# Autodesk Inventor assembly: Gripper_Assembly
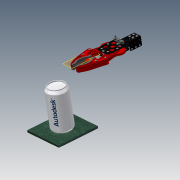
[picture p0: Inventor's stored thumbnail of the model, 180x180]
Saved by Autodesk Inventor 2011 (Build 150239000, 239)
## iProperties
Created: 2007-10
Part Number: Gripper_Assembly
Document SubType Name: Assembly
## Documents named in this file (10)
- C:\Data Folder\VEX 2011\Inventor Datasets\Unit 12\Gripper_Assembly.iam
- C:\Data Folder\VEX 2011\Inventor Datasets\Unit 12\Components\Vexplorer-Claw-Pin.iam
- C:\Data Folder\VEX 2011\Inventor Datasets\Unit 12\Components\Vexplorer-CLAW-FINGER-ASSY.iam
- C:\Data Folder\VEX 2011\Inventor Datasets\Unit 12\Components\VEX-12-TOOTH-GEAR.ipt
- C:\Data Folder\VEX 2011\Inventor Datasets\Unit 12\Components\Vexplorer-CLAW-GEAR-LINKAGE.ipt
- C:\Data Folder\VEX 2011\Inventor Datasets\Unit 12\Components\Vexplorer-CLAW-LINKAGE.ipt
- C:\Data Folder\VEX 2011\Inventor Datasets\Unit 12\Components\SHAFT-2000.ipt
- C:\Data Folder\VEX 2011\Inventor Datasets\Unit 12\Gripper_Assembly_SubAssembly.iam
- C:\Data Folder\VEX 2011\Inventor Datasets\Unit 12\Components\Base_01.ipt
- C:\Data Folder\VEX 2011\Inventor Datasets\Unit 12\Components\Can.ipt
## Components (15 placed, 9 different names)
1. Vexplorer-CLAW-FINGER-ASSY [sub-assembly] — Mate:56, Mate:57, Mate:58, Mate:63, Mate:64, Mate:65, Mate:66
2. VEX-12-TOOTH-GEAR — Mate:61, Mate:62, Mate:84, Mate:85
3. Vexplorer-CLAW-GEAR-LINKAGE — Mate:57, Mate:58, Mate:78, Mate:82, Flush:14
4. Vexplorer-CLAW-LINKAGE — Mate:55, Mate:77, Flush:13, Angle:1
5. Vexplorer-CLAW-LINKAGE — Mate:56, Mate:79, Flush:14, Angle:2
6. Vexplorer-CLAW-GEAR-LINKAGE — Flush:2, Mate:54, Mate:76, Mate:80, Flush:13
7. SHAFT-2000 — Mate:61, Mate:62, Mate:83, Flush:4, Mate:84
8. Vexplorer-Claw-Pin [sub-assembly] — Mate:67, Mate:68
9. Vexplorer-Claw-Pin [sub-assembly] — Mate:65, Mate:66
10. Vexplorer-Claw-Pin [sub-assembly] — Mate:63, Mate:64
11. Vexplorer-CLAW-FINGER-ASSY [sub-assembly] — Flush:2, Mate:54, Mate:55, Mate:67, Mate:68, Mate:69, Mate:70
12. Vexplorer-Claw-Pin [sub-assembly] — Mate:69, Mate:70
13. Gripper_Assembly_SubAssembly:1 [sub-assembly] — Mate:76, Mate:77, Mate:78, Mate:79, Mate:80, Mate:82, Mate:83, Flush:4, Mate:85, Drive Me 1, Drive Me 2, Mate:90, Angle:1, Angle:2
14. Base_01:1 — Drive Me 3, Mate:89, Drive Me 1, Drive Me 2, Mate:90
15. Can:1 — Drive Me 3, Mate:89
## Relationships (35: Mate 27, Flush 6, Angle 2)
- Flush:2: Vexplorer-CLAW-GEAR-LINKAGE ↔ Vexplorer-CLAW-FINGER-ASSY
- Mate:54: Vexplorer-CLAW-GEAR-LINKAGE ↔ Vexplorer-CLAW-FINGER-ASSY
- Mate:55: Vexplorer-CLAW-LINKAGE ↔ Vexplorer-CLAW-FINGER-ASSY
- Mate:56: Vexplorer-CLAW-FINGER-ASSY ↔ Vexplorer-CLAW-LINKAGE
- Mate:57: Vexplorer-CLAW-FINGER-ASSY ↔ Vexplorer-CLAW-GEAR-LINKAGE
- Mate:58: Vexplorer-CLAW-FINGER-ASSY ↔ Vexplorer-CLAW-GEAR-LINKAGE
- Mate:61: VEX-12-TOOTH-GEAR ↔ SHAFT-2000
- Mate:62: VEX-12-TOOTH-GEAR ↔ SHAFT-2000
- Mate:63: Vexplorer-CLAW-FINGER-ASSY ↔ Vexplorer-Claw-Pin
- Mate:64: Vexplorer-CLAW-FINGER-ASSY ↔ Vexplorer-Claw-Pin
- Mate:65: Vexplorer-CLAW-FINGER-ASSY ↔ Vexplorer-Claw-Pin
- Mate:66: Vexplorer-CLAW-FINGER-ASSY ↔ Vexplorer-Claw-Pin
- Mate:67: Vexplorer-Claw-Pin ↔ Vexplorer-CLAW-FINGER-ASSY
- Mate:68: Vexplorer-Claw-Pin ↔ Vexplorer-CLAW-FINGER-ASSY
- Mate:69: Vexplorer-CLAW-FINGER-ASSY ↔ Vexplorer-Claw-Pin
- Mate:70: Vexplorer-CLAW-FINGER-ASSY ↔ Vexplorer-Claw-Pin
- Mate:76: Vexplorer-CLAW-GEAR-LINKAGE ↔ Gripper_Assembly_SubAssembly:1
- Mate:77: Vexplorer-CLAW-LINKAGE ↔ Gripper_Assembly_SubAssembly:1
- Mate:78: Vexplorer-CLAW-GEAR-LINKAGE ↔ Gripper_Assembly_SubAssembly:1
- Mate:79: Vexplorer-CLAW-LINKAGE ↔ Gripper_Assembly_SubAssembly:1
- Mate:80: Vexplorer-CLAW-GEAR-LINKAGE ↔ Gripper_Assembly_SubAssembly:1
- Mate:82: Vexplorer-CLAW-GEAR-LINKAGE ↔ Gripper_Assembly_SubAssembly:1
- Mate:83: SHAFT-2000 ↔ Gripper_Assembly_SubAssembly:1
- Flush:4: SHAFT-2000 ↔ Gripper_Assembly_SubAssembly:1
- Mate:84: VEX-12-TOOTH-GEAR ↔ SHAFT-2000
- Mate:85: VEX-12-TOOTH-GEAR ↔ Gripper_Assembly_SubAssembly:1
- Drive Me 3 [Mate]: Base_01:1 ↔ Can:1
- Mate:89: Base_01:1 ↔ Can:1
- Drive Me 1 [Flush]: Gripper_Assembly_SubAssembly:1 ↔ Base_01:1
- Drive Me 2 [Flush]: Gripper_Assembly_SubAssembly:1 ↔ Base_01:1
- Flush:13: Vexplorer-CLAW-LINKAGE ↔ Vexplorer-CLAW-GEAR-LINKAGE
- Flush:14: Vexplorer-CLAW-GEAR-LINKAGE ↔ Vexplorer-CLAW-LINKAGE
- Mate:90: Gripper_Assembly_SubAssembly:1 ↔ Base_01:1
- Angle:1: Vexplorer-CLAW-LINKAGE ↔ Gripper_Assembly_SubAssembly:1
- Angle:2: Vexplorer-CLAW-LINKAGE ↔ Gripper_Assembly_SubAssembly:1
## Named parameters: angle = 15 deg
